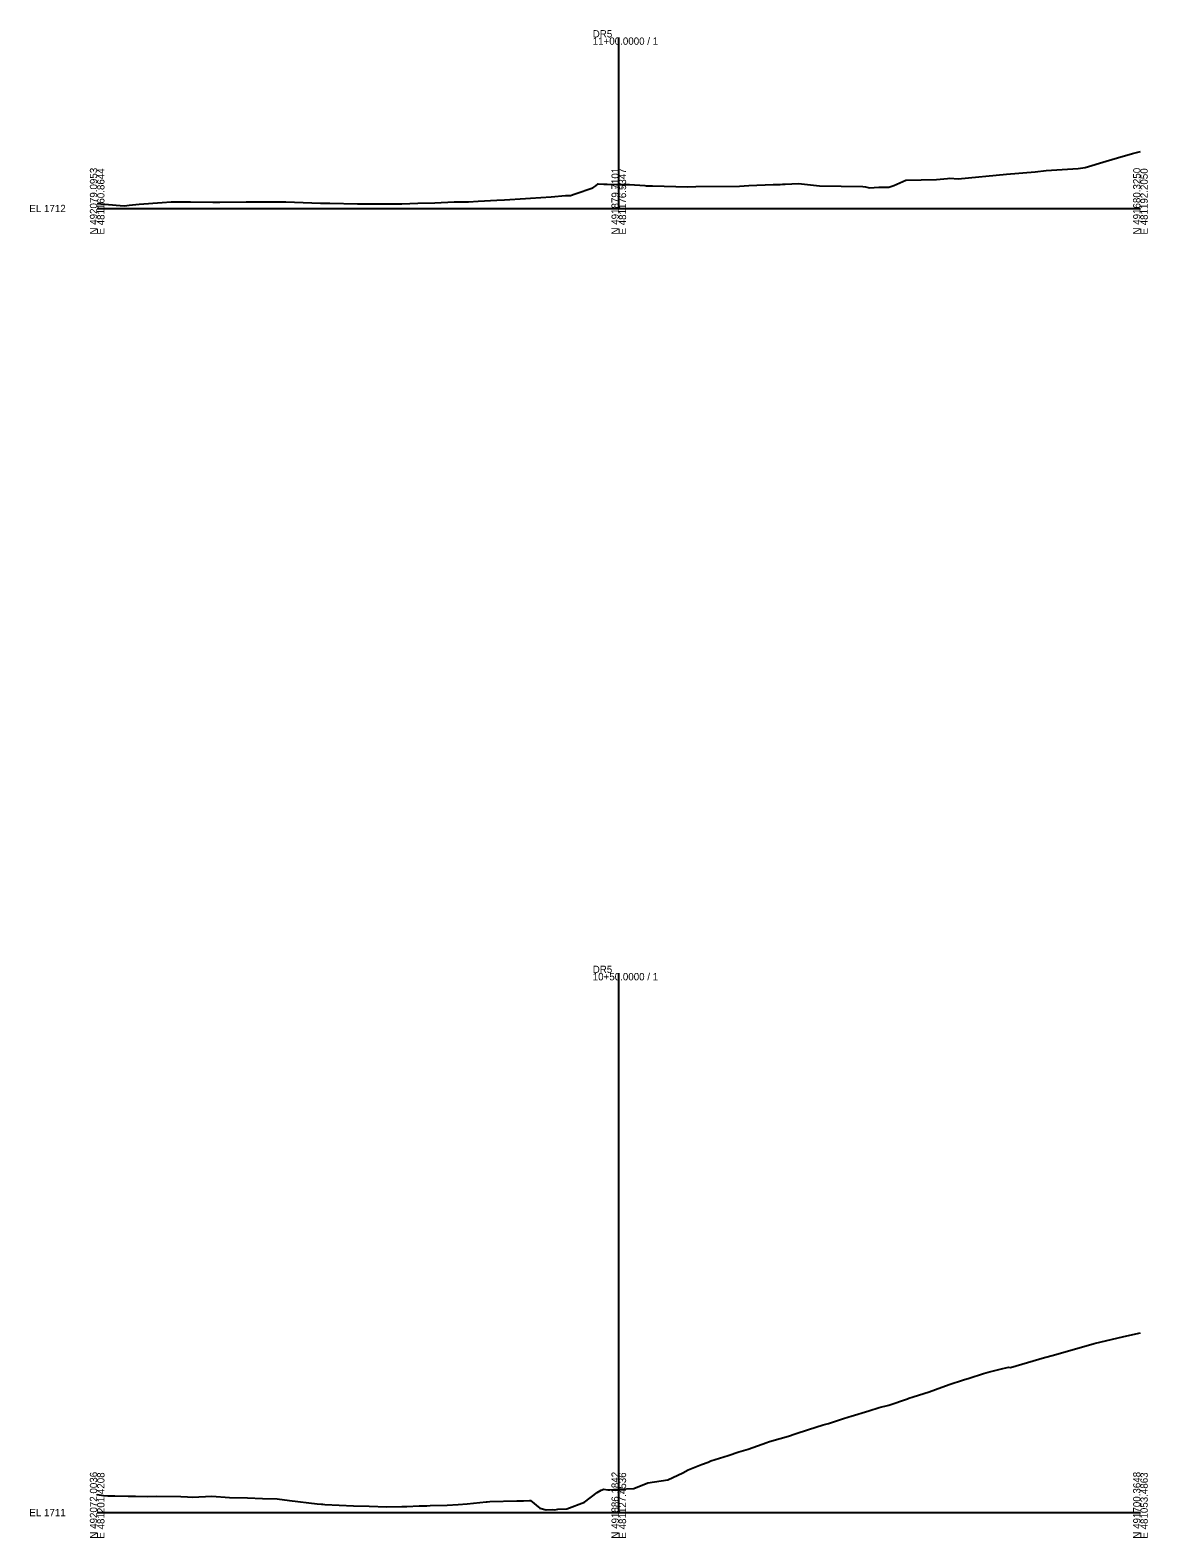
# Model space of a CAD drawing. Extents: x -26 to 403, y -10 to 2534.
# Drawn here: x -26 to 403, y 490 to 1068 of the extents above; entities that cross this region are included whole.
import ezdxf

# ---------------------------------------------------------------- set-up
doc = ezdxf.new("R2010")
doc.units = 0
for name, color, linetype in [('Exist Cross Section Cell', 7, 'Continuous'), ('Exist XS Center Line Elevation Label', 7, 'Continuous'), ('Exist XS Ground Line', 7, 'Continuous'), ('Scratch_Level_5', 7, 'Continuous')]:
    doc.layers.add(name, color=color, linetype=linetype)

msp = doc.modelspace()

# ---------------------------------------------------------------- linework, layer by layer
at = {"layer": 'Exist Cross Section Cell'}
for p, q in [((200, 1000), (200, 1065.57)), ((0, 1000), (200, 1000)), ((200, 1000), (400, 1000)), ((200, 500), (200, 706.87)), ((0, 500), (200, 500)), ((200, 500), (400, 500))]:
    msp.add_line(p, q, dxfattribs=at)
at = {"layer": 'Exist XS Ground Line'}
for points in [[(0, 1001.91), (4.36, 1001.59), (8.81, 1001.19), (10.44, 1001.02), (12.33, 1001.23), (16.13, 1001.68), (24.88, 1002.3), (28.41, 1002.51), (35.77, 1002.49), (44.4, 1002.45), (45.81, 1002.45), (47.01, 1002.44), (57.11, 1002.61), (61.21, 1002.61), (70.04, 1002.59), (72.3, 1002.51), (85.59, 1002.06), (87.5, 1002.03), (89.22, 1002.03), (99.86, 1001.82), (102.84, 1001.84), (109.74, 1001.78), (116.83, 1001.82), (122.97, 1001.99), (129.45, 1002.16), (136.86, 1002.49), (142.39, 1002.53), (146.13, 1002.81), (153.28, 1003.16), (156.17, 1003.35), (164.17, 1003.82), (166.2, 1003.95), (174.04, 1004.47), (179.62, 1004.93), (181.53, 1005.02), (183.21, 1005.65), (190.02, 1007.96), (191.2, 1008.72), (192.14, 1009.41), (194.2, 1009.32), (195.54, 1009.3), (199.07, 1009.25), (200, 1009.24), (204.14, 1009.16), (209.92, 1008.76), (210.51, 1008.71), (212.96, 1008.65), (226.4, 1008.34), (229.5, 1008.4), (246.34, 1008.62), (249.87, 1008.87), (259.16, 1009.25), (261.89, 1009.26), (262.8, 1009.3), (263.8, 1009.38), (268.84, 1009.64), (276.99, 1008.73), (293.56, 1008.44), (294.57, 1008.25), (296.07, 1007.97), (299.7, 1008.14), (300.16, 1008.15), (300.61, 1008.16), (303.52, 1008.17), (305.44, 1008.84), (310, 1010.89), (321.79, 1011.06), (326.05, 1011.56), (326.87, 1011.64), (330.1, 1011.38), (348.68, 1013.19), (359.64, 1014.1), (363.84, 1014.53), (376.07, 1015.39), (378.87, 1015.76), (386.92, 1018.11), (391.17, 1019.38), (396.95, 1021.09), (400, 1021.86)], [(0, 506.9), (2.42, 506.54), (4.07, 506.41), (6.8, 506.36), (11.91, 506.24), (14.64, 506.26), (19.28, 506.2), (22.78, 506.26), (32.06, 506.16), (34.62, 506.07), (36.6, 505.96), (43.94, 506.26), (50.68, 505.83), (57.64, 505.69), (63.45, 505.35), (69.04, 505.27), (73.8, 504.67), (84.36, 503.34), (86, 503.21), (86.5, 503.18), (87.34, 503.15), (98.34, 502.56), (104.27, 502.41), (111.06, 502.14), (116.87, 502.29), (118.76, 502.32), (123.5, 502.54), (126.46, 502.64), (127.64, 502.69), (134.16, 502.85), (138.4, 503.14), (141.86, 503.41), (149.17, 504.11), (149.56, 504.15), (150.55, 504.2), (160.89, 504.56), (163.45, 504.54), (165.79, 504.64), (166.14, 504.59), (169.77, 501.73), (172.13, 501), (174.6, 501.23), (175.46, 501.11), (176.59, 501.32), (180.12, 501.4), (186.85, 503.96), (191.75, 507.69), (193.25, 508.54), (193.56, 508.73), (194.1, 508.91), (195.79, 508.69), (196.55, 508.71), (197.94, 508.78), (200, 508.91), (205.77, 509.25), (211.13, 511.43), (218.86, 512.53), (224.53, 515.28), (226.56, 516.36), (231.68, 518.4), (234.26, 519.36), (235.29, 519.78), (241.96, 521.94), (246.06, 523.25), (249.66, 524.33), (256.82, 526.9), (257.36, 527.08), (258.72, 527.49), (265.06, 529.34), (267.59, 530.2), (272.76, 531.86), (278.35, 533.59), (280.46, 534.2), (285.77, 535.94), (288.16, 536.71), (289.12, 537.01), (295.86, 539.02), (299.88, 540.25), (303.56, 541.2), (310.65, 543.61), (311.26, 543.83), (312.81, 544.34), (318.96, 546.31), (321.41, 547.24), (326.66, 549.05), (332.18, 550.83), (334.36, 551.58), (339.86, 553.3), (341.57, 553.83), (346.17, 555.04), (349.35, 555.76), (350.14, 555.59), (363.23, 559.49), (366.7, 560.4), (382.2, 564.86), (393.69, 567.53), (400, 568.96)]]:
    msp.add_lwpolyline(points, dxfattribs=at)
at = {"layer": 'Scratch_Level_5'}
for points in [[(0, 1001.91), (4.36, 1001.59), (8.81, 1001.19), (10.44, 1001.02), (12.33, 1001.23), (16.13, 1001.68), (24.88, 1002.3), (28.41, 1002.51), (35.77, 1002.49), (44.4, 1002.45), (45.81, 1002.45), (47.01, 1002.44), (57.11, 1002.61), (61.21, 1002.61), (70.04, 1002.59), (72.3, 1002.51), (85.59, 1002.06), (87.5, 1002.03), (89.22, 1002.03), (99.86, 1001.82), (102.84, 1001.84), (109.74, 1001.78), (116.83, 1001.82), (122.97, 1001.99), (129.45, 1002.16), (136.86, 1002.49), (142.39, 1002.53), (146.13, 1002.81), (153.28, 1003.16), (156.17, 1003.35), (164.17, 1003.82), (166.2, 1003.95), (174.04, 1004.47), (179.62, 1004.93), (181.53, 1005.02), (183.21, 1005.65), (190.02, 1007.96), (191.2, 1008.72), (192.14, 1009.41), (194.2, 1009.32), (195.54, 1009.3), (199.07, 1009.25), (200, 1009.24), (204.14, 1009.16), (209.92, 1008.76), (210.51, 1008.71), (212.96, 1008.65), (226.4, 1008.34), (229.5, 1008.4), (246.34, 1008.62), (249.87, 1008.87), (259.16, 1009.25), (261.89, 1009.26), (262.8, 1009.3), (263.8, 1009.38), (268.84, 1009.64), (276.99, 1008.73), (293.56, 1008.44), (294.57, 1008.25), (296.07, 1007.97), (299.7, 1008.14), (300.16, 1008.15), (300.61, 1008.16), (303.52, 1008.17), (305.44, 1008.84), (310, 1010.89), (321.79, 1011.06), (326.05, 1011.56), (326.87, 1011.64), (330.1, 1011.38), (348.68, 1013.19), (359.64, 1014.1), (363.84, 1014.53), (376.07, 1015.39), (378.87, 1015.76), (386.92, 1018.11), (391.17, 1019.38), (396.95, 1021.09), (400, 1021.86)], [(0, 506.9), (2.42, 506.54), (4.07, 506.41), (6.8, 506.36), (11.91, 506.24), (14.64, 506.26), (19.28, 506.2), (22.78, 506.26), (32.06, 506.16), (34.62, 506.07), (36.6, 505.96), (43.94, 506.26), (50.68, 505.83), (57.64, 505.69), (63.45, 505.35), (69.04, 505.27), (73.8, 504.67), (84.36, 503.34), (86, 503.21), (86.5, 503.18), (87.34, 503.15), (98.34, 502.56), (104.27, 502.41), (111.06, 502.14), (116.87, 502.29), (118.76, 502.32), (123.5, 502.54), (126.46, 502.64), (127.64, 502.69), (134.16, 502.85), (138.4, 503.14), (141.86, 503.41), (149.17, 504.11), (149.56, 504.15), (150.55, 504.2), (160.89, 504.56), (163.45, 504.54), (165.79, 504.64), (166.14, 504.59), (169.77, 501.73), (172.13, 501), (174.6, 501.23), (175.46, 501.11), (176.59, 501.32), (180.12, 501.4), (186.85, 503.96), (191.75, 507.69), (193.25, 508.54), (193.56, 508.73), (194.1, 508.91), (195.79, 508.69), (196.55, 508.71), (197.94, 508.78), (200, 508.91), (205.77, 509.25), (211.13, 511.43), (218.86, 512.53), (224.53, 515.28), (226.56, 516.36), (231.68, 518.4), (234.26, 519.36), (235.29, 519.78), (241.96, 521.94), (246.06, 523.25), (249.66, 524.33), (256.82, 526.9), (257.36, 527.08), (258.72, 527.49), (265.06, 529.34), (267.59, 530.2), (272.76, 531.86), (278.35, 533.59), (280.46, 534.2), (285.77, 535.94), (288.16, 536.71), (289.12, 537.01), (295.86, 539.02), (299.88, 540.25), (303.56, 541.2), (310.65, 543.61), (311.26, 543.83), (312.81, 544.34), (318.96, 546.31), (321.41, 547.24), (326.66, 549.05), (332.18, 550.83), (334.36, 551.58), (339.86, 553.3), (341.57, 553.83), (346.17, 555.04), (349.35, 555.76), (350.14, 555.59)]]:
    msp.add_lwpolyline(points, dxfattribs=at)

# ---------------------------------------------------------------- texts
at = {"layer": 'Exist Cross Section Cell'}
for s, p in [('11+00.0000 / 1', (190, 1062.77)), ('DR5', (190, 1065.57)), ('EL 1712', (-26, 998.6)), ('10+50.0000 / 1', (190, 704.07)), ('DR5', (190, 706.87)), ('EL 1711', (-26, 498.6))]:
    msp.add_text(s, height=2.8, dxfattribs=at).set_placement(p)
for s, p in [('N 492079.0953', (0, 990)), ('E 481160.8644', (2.8, 990)), ('N 491879.7101', (200, 990)), ('E 481176.5347', (202.8, 990)), ('N 491680.3250', (400, 990)), ('E 481192.2050', (402.8, 990)), ('N 492072.0036', (0, 490)), ('E 481201.4208', (2.8, 490)), ('N 491886.1842', (200, 490)), ('E 481127.4536', (202.8, 490)), ('N 491700.3648', (400, 490)), ('E 481053.4863', (402.8, 490))]:
    msp.add_text(s, height=2.8, rotation=90, dxfattribs=at).set_placement(p)
at = {"layer": 'Exist XS Center Line Elevation Label'}
for s, p in [('1721.24', (198.39, 1007.66)), ('1719.91', (198.62, 507.32))]:
    msp.add_text(s, height=0.75, dxfattribs=at).set_placement(p)

doc.saveas('drawing.dxf')
